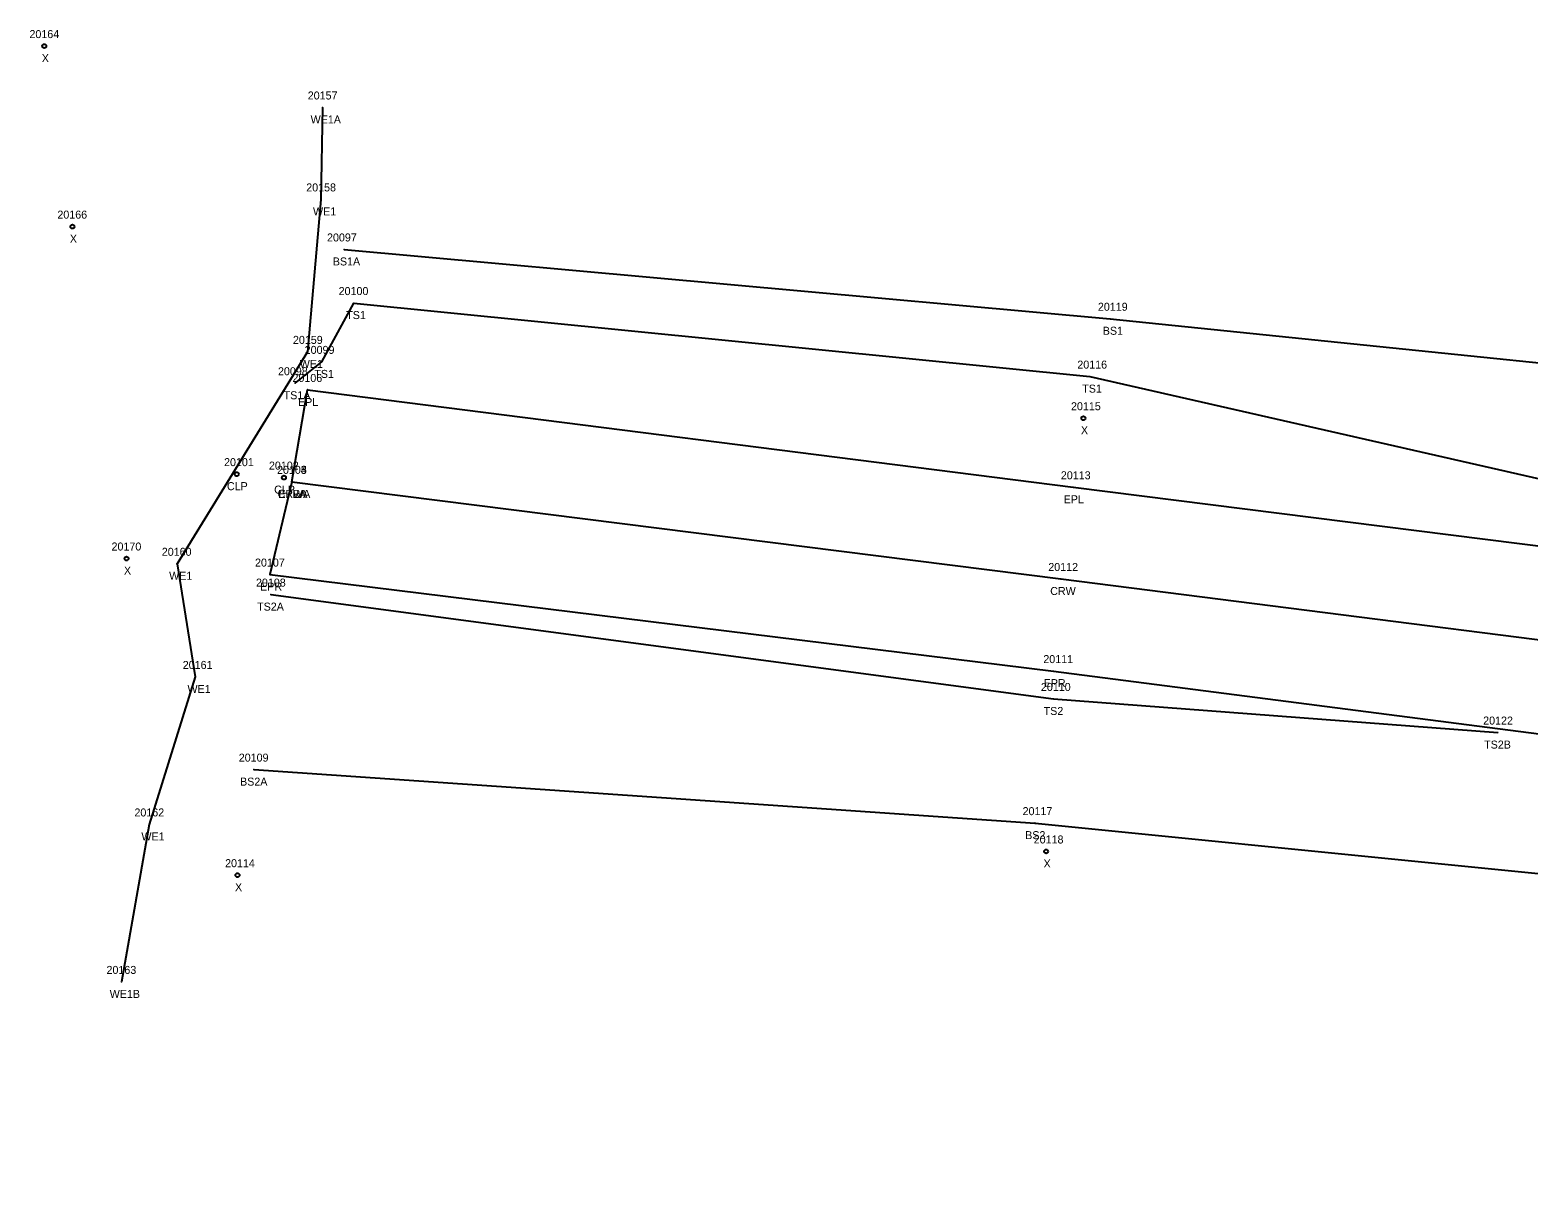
# Model space of a CAD drawing. Extents: x 2080935 to 2082049, y 730754 to 730962.
# Drawn here: x 2081534.7 to 2081721.9, y 730767 to 730910.3 of the extents above; entities that cross this region are included whole.
import ezdxf

# ---------------------------------------------------------------- set-up
doc = ezdxf.new("R2010")
doc.units = 0
for name, color, linetype in [('RD_DTM_BkLn1', 7, 'Continuous'), ('RD_DTM_BkLn2', 7, 'Continuous'), ('RD_EX_H2O', 7, 'Continuous'), ('RD_EX_H2O_txCode', 7, 'Continuous'), ('RD_EX_Road', 7, 'Continuous'), ('RD_EX_Road_txCode', 7, 'Continuous'), ('RD_Sketch8', 7, 'Continuous'), ('RD_SMD_Locator', 7, 'Continuous'), ('RD_SMD_Misc', 7, 'Continuous')]:
    doc.layers.add(name, color=color, linetype=linetype)

msp = doc.modelspace()

# ---------------------------------------------------------------- linework, layer by layer
at = {"layer": 'RD_DTM_BkLn1'}
msp.add_lwpolyline([(2081567.45, 730853.84), (2081663.53, 730841.7), (2081762.3, 730829.16), (2081864.76, 730815.62), (2081946.16, 730805.08), (2082043.01, 730792.22)], dxfattribs=at)
at = {"layer": 'RD_DTM_BkLn2'}
for points in [[(2081573.98, 730882.88), (2081669.72, 730874.22), (2081770.38, 730863.88), (2081871.58, 730845.86), (2081952.53, 730844.4), (2082047.2, 730823.74)], [(2081567.86, 730866.16), (2081571.2, 730868.83), (2081575.19, 730876.18), (2081667.17, 730866.99), (2081764.74, 730844.81), (2081867.48, 730833.13), (2081949.65, 730833.94), (2082043.99, 730810.42)], [(2081564.82, 730839.75), (2081662.64, 730826.71), (2081718.16, 730822.51)], [(2081562.68, 730817.88), (2081660.31, 730811.19), (2081763.58, 730800.86), (2081859.9, 730787.32), (2081942.25, 730773.23), (2082039.2, 730766.97)]]:
    msp.add_lwpolyline(points, dxfattribs=at)
at = {"layer": 'RD_EX_H2O'}
msp.add_lwpolyline([(2081571.26, 730900.62), (2081571.06, 730889.13), (2081569.4, 730870.08), (2081553.08, 730843.6), (2081555.37, 730829.46), (2081549.62, 730811.03), (2081546.13, 730791.35)], dxfattribs=at)
at = {"layer": 'RD_EX_Road'}
for points in [[(2081567.45, 730853.84), (2081569.41, 730865.32), (2081665.09, 730853.16), (2081763.75, 730840.72), (2081866.15, 730827.41), (2081946.59, 730817.06), (2082042.99, 730804.46)], [(2081567.45, 730853.84), (2081564.7, 730842.25), (2081662.62, 730830.19), (2081761.36, 730817.44), (2081864.07, 730804.08), (2081944.33, 730793.7), (2082046, 730780.47)]]:
    msp.add_lwpolyline(points, dxfattribs=at)
at = {"layer": 'RD_SMD_Locator'}
for centre, radius in [((2081536.49, 730908.29), 0.25), ((2081571.26, 730900.62), 0.001), ((2081571.06, 730889.13), 0.001), ((2081540.01, 730885.73), 0.25), ((2081573.98, 730882.88), 0.001), ((2081575.19, 730876.18), 0.001), ((2081669.72, 730874.22), 0.001), ((2081569.4, 730870.08), 0.001), ((2081571.2, 730868.83), 0.001), ((2081567.86, 730866.16), 0.001), ((2081569.41, 730865.32), 0.001), ((2081667.17, 730866.99), 0.001), ((2081666.36, 730861.79), 0.25), ((2081560.55, 730854.8), 0.25), ((2081566.45, 730854.37), 0.25), ((2081567.45, 730853.84), 0.001), ((2081567.45, 730853.84), 0.001), ((2081567.45, 730853.84), 0.001), ((2081665.09, 730853.16), 0.001), ((2081546.77, 730844.26), 0.25), ((2081553.08, 730843.6), 0.001), ((2081564.7, 730842.25), 0.001), ((2081663.53, 730841.7), 0.001), ((2081564.82, 730839.75), 0.001), ((2081662.62, 730830.19), 0.001), ((2081555.37, 730829.46), 0.001), ((2081662.64, 730826.71), 0.001), ((2081718.16, 730822.51), 0.001), ((2081562.68, 730817.88), 0.001), ((2081549.62, 730811.03), 0.001), ((2081660.31, 730811.19), 0.001), ((2081661.7, 730807.65), 0.25), ((2081560.64, 730804.69), 0.25), ((2081546.13, 730791.35), 0.001)]:
    msp.add_circle(centre, radius, dxfattribs=at)

# ---------------------------------------------------------------- texts
at = {"layer": 'RD_EX_H2O_txCode'}
for s, p in [('20157', (2081569.42, 730901.62)), ('WE1A', (2081569.78, 730898.62)), ('20158', (2081569.23, 730890.13)), ('WE1', (2081570.08, 730887.13)), ('20159', (2081567.57, 730871.08)), ('WE1', (2081568.42, 730868.08)), ('20160', (2081551.18, 730844.6)), ('WE1', (2081552.1, 730841.6)), ('20161', (2081553.8, 730830.46)), ('WE1', (2081554.39, 730827.46)), ('20162', (2081547.76, 730812.03)), ('WE1', (2081548.63, 730809.03)), ('20163', (2081544.27, 730792.35)), ('WE1B', (2081544.67, 730789.35))]:
    msp.add_text(s, height=1, dxfattribs=at).set_placement(p)
at = {"layer": 'RD_EX_Road_txCode'}
for s, p in [('20106', (2081567.51, 730866.32)), ('EPL', (2081568.2, 730863.32)), ('20104', (2081565.58, 730854.84)), ('20105', (2081565.58, 730854.84)), ('20113', (2081663.54, 730854.16)), ('EPRA', (2081565.73, 730851.84)), ('EPLA', (2081565.76, 730851.84)), ('EPL', (2081663.89, 730851.16)), ('20107', (2081562.83, 730843.25)), ('EPR', (2081563.47, 730840.25)), ('20111', (2081661.35, 730831.19)), ('EPR', (2081661.39, 730828.19))]:
    msp.add_text(s, height=1, dxfattribs=at).set_placement(p)
at = {"layer": 'RD_Sketch8'}
for s, p in [('20164', (2081534.64, 730909.29)), ('X', (2081536.18, 730906.29)), ('20166', (2081538.13, 730886.73)), ('X', (2081539.69, 730883.73)), ('20115', (2081664.81, 730862.79)), ('X', (2081666.05, 730859.79)), ('20170', (2081544.9, 730845.26)), ('X', (2081546.45, 730842.26)), ('20118', (2081660.15, 730808.65)), ('20114', (2081559.09, 730805.69)), ('X', (2081661.38, 730805.65)), ('X', (2081560.33, 730802.69))]:
    msp.add_text(s, height=1, dxfattribs=at).set_placement(p)
at = {"layer": 'RD_SMD_Misc'}
for s, p in [('20097', (2081571.83, 730883.88)), ('BS1A', (2081572.55, 730880.88)), ('20100', (2081573.28, 730877.18)), ('TS1', (2081574.23, 730874.18)), ('20119', (2081668.17, 730875.22)), ('BS1', (2081668.78, 730872.22)), ('20099', (2081569.04, 730869.83)), ('20116', (2081665.6, 730867.99)), ('20098', (2081565.7, 730867.16)), ('TS1', (2081570.24, 730866.83)), ('TS1', (2081666.21, 730864.99)), ('TS1A', (2081566.41, 730864.16)), ('20101', (2081558.96, 730855.8)), ('20102', (2081564.57, 730855.37)), ('20103', (2081565.58, 730854.84)), ('CLP', (2081559.32, 730852.8)), ('CLP', (2081565.22, 730852.37)), ('CRWA', (2081565.65, 730851.84)), ('20112', (2081661.97, 730842.7)), ('20108', (2081562.95, 730840.75)), ('CRW', (2081662.21, 730839.7)), ('TS2A', (2081563.09, 730837.75)), ('20110', (2081661.05, 730827.71)), ('TS2', (2081661.39, 730824.71)), ('20122', (2081716.32, 730823.51)), ('TS2B', (2081716.44, 730820.51)), ('20109', (2081560.8, 730818.88)), ('BS2A', (2081560.96, 730815.88)), ('20117', (2081658.76, 730812.19)), ('BS2', (2081659.08, 730809.19))]:
    msp.add_text(s, height=1, dxfattribs=at).set_placement(p)

doc.saveas('drawing.dxf')
